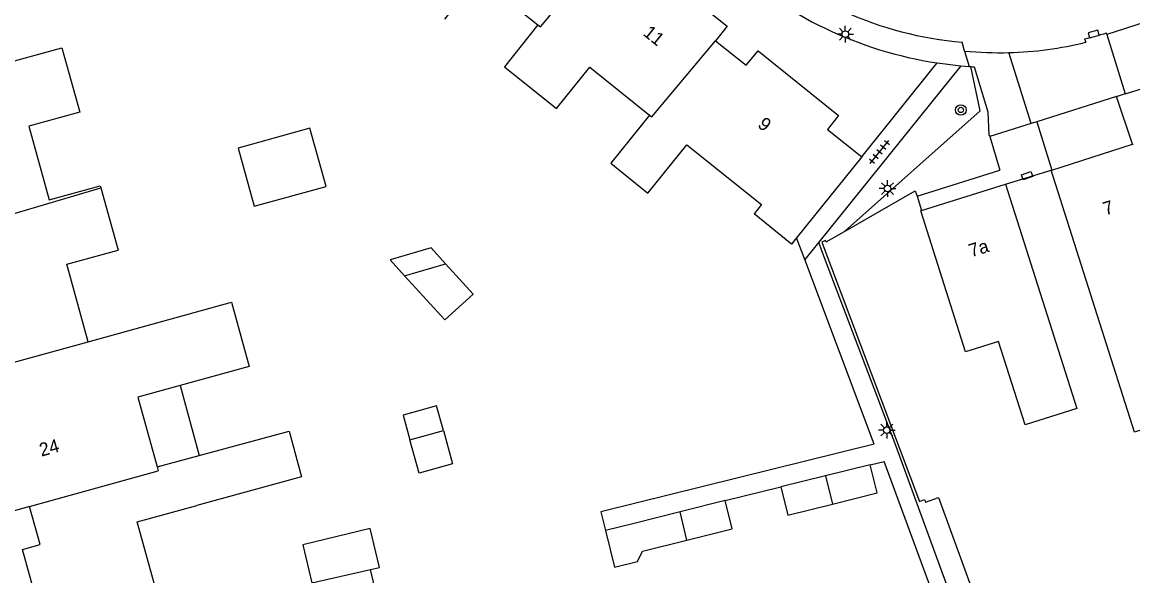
# Model space of a CAD drawing. Extents: x 136000 to 138005, y 398500 to 400500.
# Drawn here: x 137374 to 137457.7, y 398873.8 to 398915.6 of the extents above; entities that cross this region are included whole.
import ezdxf

# ---------------------------------------------------------------- set-up
doc = ezdxf.new("R2010")
doc.units = 0
for name, color, linetype in [('gg-afsc-erfafscheiding', 7, 'Continuous'), ('gg-afsc-muur', 7, 'Continuous'), ('gg-anno-huisnummerreeks BGT', 7, 'Continuous'), ('gg-bbg-gedigitaliseerde bebouwing', 7, 'Continuous'), ('gg-bbg-gedigitaliseerde bijgebouw', 7, 'Continuous'), ('gg-bbg-hoofdgebouw', 7, 'Continuous'), ('gg-bbg-luifel en loopbrug', 7, 'Continuous'), ('gg-bbg-tussenscheiding', 7, 'Continuous'), ('gg-knt-verharding', 7, 'Continuous'), ('gg-knt-verharding nz', 7, 'Continuous'), ('gt-grn-groengrens', 7, 'Continuous'), ('gt-grn-vlakafsluiter', 7, 'Continuous'), ('gt-grn-weggrens', 7, 'Continuous'), ('gt-symb-boom', 7, 'Continuous'), ('gt-symb-kolk', 7, 'Continuous'), ('gt-symb-kolk center center', 7, 'Continuous'), ('gt-symb-lichtmast', 7, 'Continuous'), ('gt-symb-tegel verharding', 7, 'Continuous')]:
    doc.layers.add(name, color=color, linetype=linetype)

# ---------------------------------------------------------------- blocks, each defined once
blk = doc.blocks.new('gt0-KOLK')
at = {"layer": 'gt-symb-kolk'}
blk.add_lwpolyline([(0, 0), (0.375, 0), (0.375, 0.4), (-0.375, 0.4), (-0.375, 0), (0, 0)], dxfattribs=at)
blk = doc.blocks.new('gt0-LMAST')
at = {"layer": 'gt-symb-lichtmast'}
for p, q in [((-0.182, 0.173), (-0.447, 0.438)), ((-0.005, 0.246), (-0.005, 0.621)), ((0.172, 0.173), (0.437, 0.438)), ((-0.255, -0.004), (-0.63, -0.004)), ((-0.182, -0.181), (-0.447, -0.446)), ((-0.005, -0.254), (-0.005, -0.629)), ((0.437, -0.446), (0.172, -0.181)), ((0.245, -0.004), (0.62, -0.004))]:
    blk.add_line(p, q, dxfattribs=at)
blk.add_circle((-0.005, -0.004), 0.25, dxfattribs=at)
blk = doc.blocks.new('gt0-BOOM')
at = {"layer": 'gt-symb-boom'}
for radius in [0.4, 0.2]:
    blk.add_circle((0, 0), radius, dxfattribs=at)
blk = doc.blocks.new('gt0-TEG1')
at = {"layer": 'gt-symb-tegel verharding'}
for p, q in [((-1.125, 0), (1.125, 0)), ((-0.9, -0.25), (-0.9, 0.25)), ((-0.45, -0.25), (-0.45, 0.25)), ((0, -0.25), (0, 0.25)), ((0.45, -0.25), (0.45, 0.25)), ((0.9, -0.25), (0.9, 0.25))]:
    blk.add_line(p, q, dxfattribs=at)
blk = doc.blocks.new('gt0-KOLKCC')
at = {"layer": 'gt-symb-kolk center center'}
blk.add_lwpolyline([(-0.375, 0.2), (0.375, 0.2), (0.375, -0.2), (-0.375, -0.2)], close=True, dxfattribs=at)

msp = doc.modelspace()

# ---------------------------------------------------------------- linework, layer by layer
at = {"layer": 'gg-afsc-erfafscheiding'}
for p, q in [((137441.469, 398902.421), (137441.807, 398901.351)), ((137434.622, 398898.981), (137435.993, 398899.77)), ((137433.013, 398897.658), (137432.399, 398899.297)), ((137438.232, 398883.727), (137433.013, 398897.658)), ((137437.94, 398882.177), (137438.991, 398882.43)), ((137427.016, 398879.469), (137431.204, 398880.5)), ((137443.078, 398879.711), (137457.686, 398839.676)), ((137400.626, 398872.887), (137400.278, 398874.279))]:
    msp.add_line(p, q, dxfattribs=at)
for points in [[(137435.993, 398899.77), (137441.335, 398902.845), (137441.469, 398902.421)], [(137438.232, 398883.727), (137417.643, 398878.626), (137417.991, 398877.219)]]:
    msp.add_lwpolyline(points, dxfattribs=at)
at = {"layer": 'gg-afsc-muur'}
msp.add_line((137443.52, 398870.11), (137438.991, 398882.43), dxfattribs=at)
msp.add_lwpolyline([(137434.622, 398898.981), (137434.573, 398899.085), (137434.288, 398898.953), (137441.645, 398879.406), (137442.029, 398879.551), (137442.106, 398879.345), (137443.078, 398879.711)], dxfattribs=at)
at = {"layer": 'gg-bbg-gedigitaliseerde bebouwing'}
for p, q in [((137412.905, 398915.346), (137410.395, 398912.197)), ((137377.033, 398913.627), (137378.389, 398908.775)), ((137410.395, 398912.197), (137414.304, 398909.048)), ((137421.307, 398908.551), (137418.394, 398904.921)), ((137418.394, 398904.921), (137421.197, 398902.667)), ((137379.932, 398903.211), (137379.974, 398903.057)), ((137379.974, 398903.057), (137381.27, 398898.361)), ((137432.016, 398898.821), (137429.205, 398901.109)), ((137384.221, 398882.008), (137387.391, 398882.874))]:
    msp.add_line(p, q, dxfattribs=at)
for points in [[(137405.884, 398915.793), (137408.394, 398918.942), (137412.905, 398915.346)], [(137372.666, 398913.319), (137373.007, 398912.502), (137377.033, 398913.627)], [(137414.304, 398909.048), (137416.804, 398912.164), (137421.307, 398908.551)], [(137378.389, 398908.775), (137374.533, 398907.713), (137376.066, 398902.146), (137379.932, 398903.211)], [(137421.197, 398902.667), (137424.124, 398906.315), (137429.757, 398901.797), (137429.205, 398901.109)], [(137379.013, 398891.446), (137377.418, 398897.314), (137381.27, 398898.361)], [(137379.013, 398891.446), (137389.807, 398894.435), (137391.152, 398889.58), (137385.939, 398888.143)], [(137385.939, 398888.143), (137382.764, 398887.268), (137384.221, 398882.008)], [(137387.391, 398882.874), (137394.151, 398884.722), (137395.098, 398881.256), (137387.214, 398879.101)], [(137384.714, 398870.615), (137382.718, 398877.862), (137387.214, 398879.101)]]:
    msp.add_lwpolyline(points, dxfattribs=at)
at = {"layer": 'gg-bbg-gedigitaliseerde bijgebouw'}
for p, q in [((137401.773, 398897.632), (137402.861, 398896.434)), ((137402.861, 398896.434), (137405.949, 398897.336)), ((137403.259, 398884.065), (137405.782, 398884.761)), ((137437.94, 398882.177), (137434.562, 398881.336)), ((137434.562, 398881.336), (137431.204, 398880.5)), ((137427.016, 398879.469), (137423.615, 398878.62)), ((137423.615, 398878.62), (137420.262, 398877.782)), ((137420.262, 398877.782), (137417.991, 398877.219)), ((137420.795, 398875.647), (137424.133, 398876.481)), ((137395.875, 398873.276), (137400.278, 398874.279))]:
    msp.add_line(p, q, dxfattribs=at)
for points in [[(137396.938, 398903.163), (137395.73, 398907.554), (137390.313, 398906.065), (137391.521, 398901.673), (137396.938, 398903.163)], [(137405.949, 398897.336), (137404.861, 398898.533), (137401.773, 398897.632)], [(137405.782, 398884.761), (137406.478, 398882.237), (137403.954, 398881.542), (137403.259, 398884.065)], [(137435.1, 398879.209), (137438.47, 398880.048), (137437.94, 398882.177)], [(137431.204, 398880.5), (137431.734, 398878.371), (137435.1, 398879.209)], [(137424.133, 398876.481), (137427.549, 398877.334), (137427.016, 398879.469)], [(137400.278, 398874.279), (137400.969, 398874.436), (137400.255, 398877.379), (137395.178, 398876.146), (137395.875, 398873.276)], [(137417.991, 398877.219), (137418.678, 398874.449), (137420.416, 398874.88), (137420.795, 398875.647)]]:
    msp.add_lwpolyline(points, dxfattribs=at)
at = {"layer": 'gg-bbg-hoofdgebouw'}
for p, q in [((137451.616, 398904.405), (137457.693, 398906.343)), ((137457.693, 398906.343), (137457.758, 398906.364)), ((137437.31, 398905.394), (137432.399, 398899.297)), ((137451.576, 398904.392), (137451.616, 398904.405)), ((137441.807, 398901.351), (137448.123, 398903.344)), ((137441.75, 398901.333), (137441.807, 398901.351)), ((137432.399, 398899.297), (137432.016, 398898.821)), ((137374.596, 398879.024), (137373.291, 398878.66))]:
    msp.add_line(p, q, dxfattribs=at)
for points in [[(137417.244, 398920.178), (137419.572, 398918.294), (137421.065, 398920.154), (137427.16, 398915.25), (137426.287, 398914.159)], [(137426.287, 398914.159), (137428.584, 398912.319), (137429.511, 398913.391), (137435.561, 398908.513), (137434.73, 398907.472), (137437.31, 398905.394)], [(137460.833, 398885.594), (137457.843, 398884.645), (137451.576, 398904.392)], [(137448.123, 398903.344), (137453.505, 398886.413), (137449.612, 398885.176), (137447.608, 398891.48), (137445.126, 398890.691), (137441.75, 398901.333)], [(137376.16, 398868.237), (137374.072, 398875.776), (137375.407, 398876.154), (137374.596, 398879.024)]]:
    msp.add_lwpolyline(points, dxfattribs=at)
at = {"layer": 'gg-bbg-luifel en loopbrug'}
msp.add_line((137385.939, 398888.143), (137387.391, 398882.874), dxfattribs=at)
for points in [[(137402.861, 398896.434), (137405.882, 398893.109), (137408.022, 398895.054), (137405.949, 398897.336)], [(137405.782, 398884.761), (137405.272, 398886.613), (137402.748, 398885.917), (137403.259, 398884.065)]]:
    msp.add_lwpolyline(points, dxfattribs=at)
at = {"layer": 'gg-bbg-tussenscheiding'}
for p, q in [((137372.235, 398900.778), (137379.974, 398903.057)), ((137372.72, 398889.703), (137379.013, 398891.446)), ((137384.221, 398882.008), (137384.299, 398881.728)), ((137374.596, 398879.024), (137384.299, 398881.728)), ((137434.562, 398881.336), (137435.1, 398879.209)), ((137424.133, 398876.481), (137423.615, 398878.62))]:
    msp.add_line(p, q, dxfattribs=at)
for points in [[(137412.905, 398915.346), (137413.087, 398915.201), (137417.244, 398920.178)], [(137421.307, 398908.551), (137421.486, 398908.407), (137426.287, 398914.159)]]:
    msp.add_lwpolyline(points, dxfattribs=at)
at = {"layer": 'gg-knt-verharding'}
for p, q in [((137444.757, 398912.262), (137434.06, 398898.96)), ((137437.31, 398905.394), (137442.977, 398912.482)), ((137442.977, 398912.482), (137444.757, 398912.262)), ((137444.757, 398912.262), (137445.401, 398912.215)), ((137445.401, 398912.215), (137445.526, 398912.206)), ((137457.163, 398910.143), (137460.073, 398911.051)), ((137456.507, 398909.938), (137450.497, 398908.044)), ((137457.693, 398906.343), (137456.507, 398909.938)), ((137450.077, 398907.912), (137446.964, 398906.932)), ((137450.497, 398908.044), (137450.077, 398907.912)), ((137450.497, 398908.044), (137451.616, 398904.405)), ((137446.964, 398906.932), (137447.719, 398904.397)), ((137441.469, 398902.421), (137447.719, 398904.397)), ((137434.302, 398898.32), (137434.06, 398898.96))]:
    msp.add_line(p, q, dxfattribs=at)
for points in [[(137445.785, 398912.191), (137446.802, 398908.803), (137446.882, 398907.044), (137446.932, 398907.039), (137446.964, 398906.932)], [(137457.163, 398910.143), (137456.536, 398909.947), (137456.507, 398909.938)], [(137449.159, 398858.192), (137439.86, 398883.637), (137434.302, 398898.32)]]:
    msp.add_lwpolyline(points, dxfattribs=at)
for centre, radius, start, end in [((137447.299, 398941.579), 27.649, 226.75984, 264.93492), ((137447.544, 398942.151), 30.019, 227.4045, 261.24846), ((137446.411, 398925.242), 13.066, 266.11656, 267.25427)]:
    msp.add_arc(centre, radius, start, end, dxfattribs=at)
at = {"layer": 'gg-knt-verharding nz'}
for p, q in [((137458.648, 398915.545), (137455.767, 398914.633)), ((137455.767, 398914.633), (137455.734, 398914.741)), ((137455.767, 398914.633), (137457.163, 398910.143)), ((137445.055, 398913.378), (137444.858, 398914.038)), ((137454.097, 398914.292), (137454.177, 398914.04)), ((137445.055, 398913.378), (137445.401, 398912.215)), ((137450.077, 398907.912), (137448.392, 398913.26))]:
    msp.add_line(p, q, dxfattribs=at)
for centre, radius, start, end in [((137450.216, 398931.651), 17.787, 282.60308, 288.07294), ((137447.681, 398940.377), 27.127, 271.50229, 283.85564), ((137447.688, 398940.592), 27.341, 264.47398, 271.47563)]:
    msp.add_arc(centre, radius, start, end, dxfattribs=at)
at = {"layer": 'gt-grn-groengrens'}
msp.add_lwpolyline([(137435.993, 398899.77), (137446.219, 398908.856), (137445.526, 398912.206)], dxfattribs=at)
at = {"layer": 'gt-grn-vlakafsluiter'}
msp.add_line((137448.123, 398903.344), (137451.576, 398904.392), dxfattribs=at)
at = {"layer": 'gt-grn-weggrens'}
msp.add_line((137434.06, 398898.96), (137433.013, 398897.658), dxfattribs=at)

# ---------------------------------------------------------------- block references
at = {"layer": 'gt-symb-boom'}
msp.add_blockref('gt0-BOOM', (137444.772, 398908.932), dxfattribs=at)
at = {"layer": 'gt-symb-kolk', "rotation": 15.054101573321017}
msp.add_blockref('gt0-KOLK', (137454.834, 398914.474), dxfattribs=at)
at = {"layer": 'gt-symb-kolk center center', "rotation": 18.73096927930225}
msp.add_blockref('gt0-KOLKCC', (137449.763, 398903.98), dxfattribs=at)
at = {"layer": 'gt-symb-lichtmast'}
for p in [(137436.071, 398914.656), (137439.247, 398903.011), (137439.196, 398884.793)]:
    msp.add_blockref('gt0-LMAST', p, dxfattribs=at)
at = {"layer": 'gt-symb-tegel verharding', "rotation": 51.170175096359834}
msp.add_blockref('gt0-TEG1', (137438.637, 398905.76), dxfattribs=at)

# ---------------------------------------------------------------- texts
at = {"layer": 'gg-anno-huisnummerreeks BGT'}
for s, rotation, p in [('11', 321.2, (137420.758, 398914.623)), ('9', 321.1, (137429.392, 398907.707)), ('7', 17.7, (137455.665, 398900.973)), ('7a', 17.5, (137445.549, 398897.813)), ('24', 15.6, (137375.491, 398882.782))]:
    msp.add_text(s, height=1, rotation=rotation, dxfattribs=at).set_placement(p)

doc.saveas('drawing.dxf')
